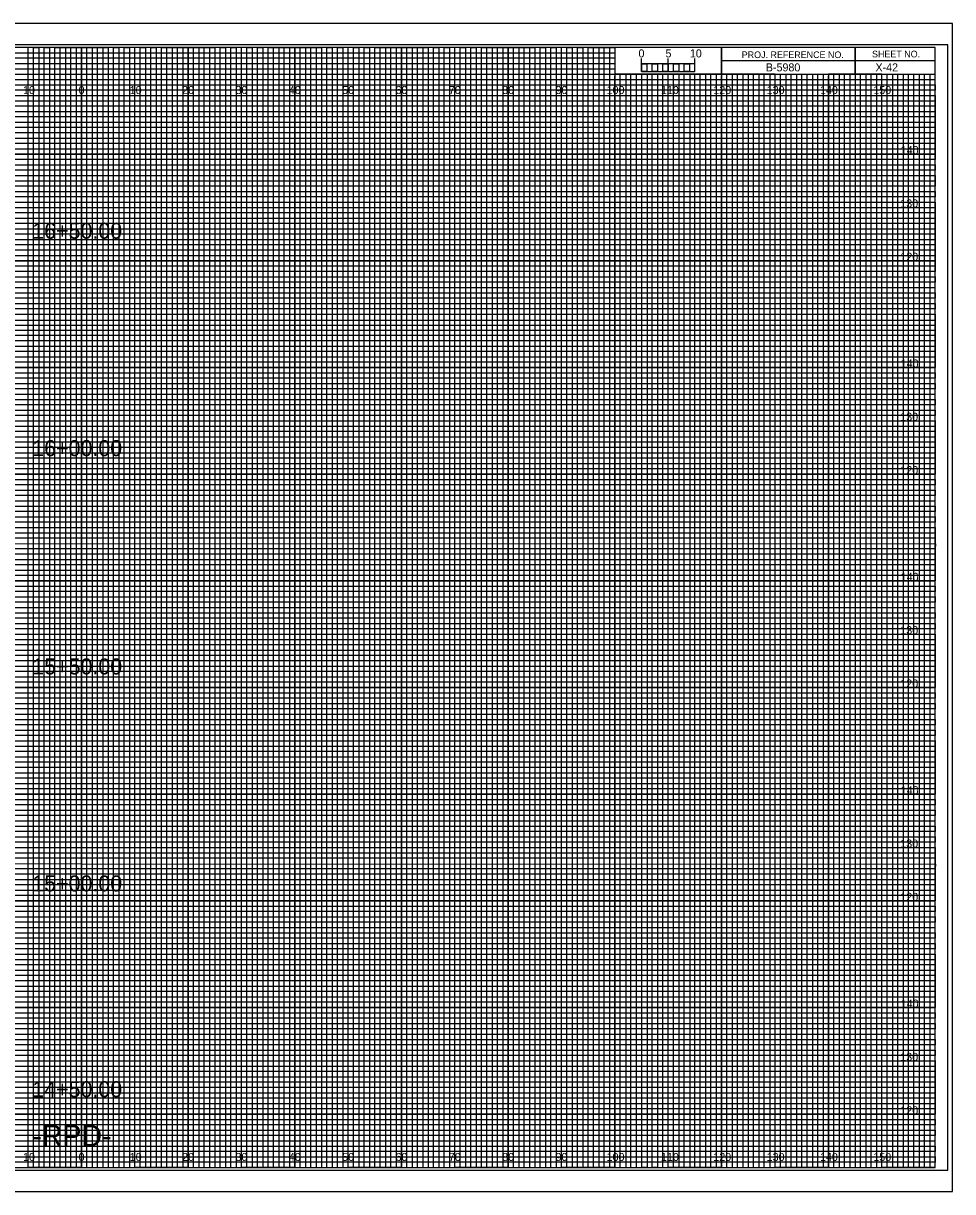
# Model space of a CAD drawing. Extents: x -13 to 323, y -5 to 874.
# Drawn here: x 149.1 to 323.3, y -4.5 to 214.5 of the extents above; entities that cross this region are included whole.
import ezdxf

# ---------------------------------------------------------------- set-up
doc = ezdxf.new("R2010")
doc.units = 0
for name, color, linetype in [('Exist Cross Section Cell', 7, 'Continuous'), ('Exist XS Center Line Elevation Label', 7, 'Continuous'), ('Exist XS Ground Line', 7, 'Continuous'), ('Prop CMT Conc Surface', 7, 'Continuous'), ('Prop CMT Concrete Structures', 7, 'Continuous'), ('Prop CMT Pvmt Course 1', 7, 'Continuous'), ('Prop CMT Pvmt Course 1 CG', 7, 'Continuous'), ('Prop CMT Pvmt Course 2', 7, 'Continuous'), ('Prop CMT Pvmt Course 3', 7, 'Continuous'), ('Prop CMT Pvmt Surface', 7, 'Continuous'), ('Prop CMT Pvmt Surface Shoulder', 7, 'Continuous'), ('Prop CMT Shld Paved Course 1', 7, 'Continuous'), ('Prop CMT Shld Paved Course 2', 7, 'Continuous'), ('Prop CMT Shld Paved Course 3', 7, 'Continuous'), ('Prop CMT Slope Grass', 7, 'Continuous'), ('Prop CMT Subgrade Earthwork', 7, 'Continuous'), ('Scratch_Level_1', 7, 'Continuous')]:
    doc.layers.add(name, color=color, linetype=linetype)

msp = doc.modelspace()

# ---------------------------------------------------------------- linework, layer by layer
at = {"layer": 'Exist XS Center Line Elevation Label'}
for points in [[(145, 0), (155, 0), (155, 210), (165, 210), (165, 0), (175, 0), (175, 210), (185, 210), (185, 0), (195, 0), (195, 210), (205, 210), (205, 0), (215, 0), (215, 210), (225, 210), (225, 0), (235, 0), (235, 210), (245, 210), (245, 0), (255, 0), (255, 210), (259.93, 210), (260, 210), (260, 205), (264.99, 205), (264.99, 0), (275, 0), (275, 205), (285, 205), (285, 0), (295, 0), (295, 205), (305, 205), (305, 0), (315, 0), (315, 205)], [(0, 205), (275, 205)], [(0, 185), (320, 185), (320, 195), (0, 195)], [(0, 165), (320, 165), (320, 175), (0, 175)], [(0, 145), (320, 145), (320, 155), (0, 155)], [(0, 125), (320, 125), (320, 135), (0, 135)], [(0, 105), (320, 105), (320, 115), (0, 115)], [(0, 85), (320, 85), (320, 95), (0, 95)], [(0, 65), (320, 65), (320, 75), (0, 75)], [(0, 45), (320, 45), (320, 55), (0, 55)], [(0, 25), (320, 25), (320, 35), (0, 35)], [(0, 5), (320, 5), (320, 15), (0, 15)]]:
    msp.add_lwpolyline(points, dxfattribs=at)
at = {"layer": 'Exist XS Ground Line'}
for p, q in [((150, 210), (140, 210)), ((150, 0), (150, 210)), ((170, 210), (160, 210)), ((160, 210), (160, 0)), ((170, 0), (170, 210)), ((190, 210), (180, 210)), ((180, 210), (180, 0)), ((190, 0), (190, 210)), ((210, 210), (200, 210)), ((200, 210), (200, 0)), ((210, 0), (210, 210)), ((230, 210), (220, 210)), ((220, 210), (220, 0)), ((230, 0), (230, 210)), ((250, 210), (240, 210)), ((240, 210), (240, 0)), ((250, 0), (250, 210)), ((260, 210), (260, 0)), ((270, 0), (270, 205)), ((290, 205), (280, 205)), ((280, 205), (280, 0)), ((290, 0), (290, 205)), ((310, 205), (300, 205)), ((300, 205), (300, 0)), ((310, 0), (310, 205)), ((160, 0), (150, 0)), ((180, 0), (170, 0)), ((200, 0), (190, 0)), ((220, 0), (210, 0)), ((240, 0), (230, 0)), ((260, 0), (250, 0)), ((280, 0), (270, 0)), ((300, 0), (290, 0)), ((320, 0), (310, 0)), ((320, 0), (320, 0))]:
    msp.add_line(p, q, dxfattribs=at)
for points in [[(0, 200), (320, 200), (320, 190), (0, 190)], [(0, 180), (320, 180), (320, 170), (0, 170)], [(0, 160), (320, 160), (320, 150), (0, 150)], [(0, 140), (320, 140), (320, 130), (0, 130)], [(0, 120), (320, 120), (320, 110), (0, 110)], [(0, 100), (320, 100), (320, 90), (0, 90)], [(0, 80), (320, 80), (320, 70), (0, 70)], [(0, 60), (320, 60), (320, 50), (0, 50)], [(0, 40), (320, 40), (320, 30), (0, 30)], [(0, 20), (320, 20), (320, 10), (0, 10)]]:
    msp.add_lwpolyline(points, dxfattribs=at)
at = {"layer": 'Prop CMT Pvmt Course 2'}
for p, q in [((265, 205.49), (265, 207.9)), ((265, 206.9), (265, 207.9)), ((270, 205.49), (270, 207.9)), ((275, 205.49), (275, 207.9)), ((275, 206.9), (275, 207.9))]:
    msp.add_line(p, q, dxfattribs=at)
for points in [[(275, 206.9), (265, 206.9), (265, 205.49), (275, 205.49)], [(265, 206.9), (266, 206.9), (266, 205.49), (265, 205.49)], [(267, 206.9), (268, 206.9), (268, 205.49), (267, 205.49)], [(269, 206.9), (270, 206.9), (270, 205.49), (269, 205.49)], [(271, 206.9), (272, 206.9), (272, 205.49), (271, 205.49)], [(273, 206.9), (274, 206.9), (274, 205.49), (273, 205.49)]]:
    msp.add_lwpolyline(points, close=True, dxfattribs=at)
at = {"layer": 'Prop CMT Pvmt Course 3'}
msp.add_lwpolyline([(-13.4, -4.5), (323.3, -4.5), (323.3, 214.5), (-13.4, 214.5)], close=True, dxfattribs=at)
at = {"layer": 'Prop CMT Pvmt Surface'}
for p, q in [((150, 0), (150, 210)), ((160, 0), (160, 210)), ((170, 0), (170, 210)), ((180, 0), (180, 210)), ((190, 0), (190, 210)), ((200, 0), (200, 210)), ((210, 0), (210, 210)), ((220, 0), (220, 210)), ((230, 0), (230, 210)), ((240, 0), (240, 210)), ((250, 0), (250, 210)), ((260, 0), (260, 204.69)), ((270, 0), (270, 204.69)), ((280, 0), (280, 204.69)), ((290, 0), (290, 204.69)), ((300, 0), (300, 204.69)), ((310, 0), (310, 204.69)), ((0, 200), (320, 200)), ((0, 190), (320, 190)), ((0, 180), (320, 180)), ((0, 170), (320, 170)), ((0, 160), (320, 160)), ((0, 150), (320, 150)), ((0, 140), (320, 140)), ((0, 130), (320, 130)), ((0, 120), (320, 120)), ((0, 110), (320, 110)), ((0, 100), (320, 100)), ((0, 90), (320, 90)), ((0, 80), (320, 80)), ((0, 70), (320, 70)), ((0, 60), (320, 60)), ((0, 50), (320, 50)), ((0, 40), (320, 40)), ((0, 30), (320, 30)), ((0, 20), (320, 20)), ((0, 10), (320, 10))]:
    msp.add_line(p, q, dxfattribs=at)
at = {"layer": 'Prop CMT Pvmt Surface Shoulder'}
for p, q in [((323.3, 214.5), (-13.4, 214.5)), ((-13.4, -4.5), (323.3, -4.5))]:
    msp.add_line(p, q, dxfattribs=at)
at = {"layer": 'Prop CMT Shld Paved Course 1'}
for p, q in [((0, 209), (260, 209)), ((260, 209), (260, 207.98)), ((260, 207.98), (0, 207.98)), ((0, 207), (260, 207)), ((260, 205.89), (0, 205.89)), ((260, 207), (260, 205.89)), ((0, 204), (320, 204))]:
    msp.add_line(p, q, dxfattribs=at)
for points in [[(0, 203), (270, 203), (320, 203), (320, 202), (0, 202)], [(0, 201), (320, 201), (320, 199), (0, 199)], [(0, 198), (320, 198), (320, 197), (0, 196.98)], [(0, 196), (320, 196), (320, 194), (0, 194)], [(0, 193), (320, 193), (320, 192), (0, 192)], [(0, 191), (320, 191), (320, 189), (0, 189)], [(0, 188), (320, 188), (320, 187), (0, 187)], [(0, 186), (320, 186), (320, 184), (0, 184)], [(0, 183), (320, 183), (320, 182), (0, 182)], [(0, 181), (320, 181), (320, 179), (0, 179)], [(0, 178), (320, 178), (320, 177), (0, 177)], [(0, 176), (320, 176), (320, 173.95), (320, 173), (320, 172), (0, 172)], [(0, 174), (320, 174), (320, 173), (0, 173)], [(0, 171), (320, 171), (320, 169), (0, 169.03)], [(0, 169.03), (320, 169), (320, 168), (0, 168)], [(0, 167), (320, 167), (320, 166), (0, 166)], [(0, 164), (320, 164), (320, 163), (0, 163)], [(0, 162), (320, 162), (320, 161), (0, 161)], [(-0.07, 158.89), (320, 158.89), (320, 157.88), (-0.07, 157.88)], [(0, 157), (320, 157), (320, 156), (0, 156)], [(0, 154), (320, 154), (320, 153), (0, 153)], [(0, 152), (320, 152), (320, 151), (0, 151)], [(0, 149), (320, 149), (320, 148), (0, 148)], [(0, 147), (320, 147), (320, 146), (0, 146)], [(0, 144), (320, 144), (320, 143), (0, 143)], [(0, 142), (320, 142), (320, 141), (0, 141)], [(0, 139), (320, 139), (319.99, 137.98), (0, 138)], [(0, 137), (320, 137), (320, 136), (0, 136)], [(0, 134), (320, 134), (320, 133), (0, 133)], [(0, 132), (320, 132), (320, 131), (0, 131)], [(0, 129), (320, 129), (320, 128), (0, 128)], [(0, 127), (320, 127), (320, 126), (0, 126)], [(0, 124), (320, 124), (320, 123), (0, 123)], [(0, 122), (320, 122), (320, 121), (0, 121)], [(0, 119), (320, 119), (320, 118), (0, 118)], [(0, 116.99), (320.07, 116.91), (320, 116), (0, 116)], [(0, 114), (320, 114), (320, 113), (0, 113)], [(0, 112), (320, 112), (320, 111), (0, 111)], [(0, 109), (320, 109), (320, 108), (0, 108)], [(0, 107), (320, 107), (320, 106), (0, 106)], [(0, 104), (320, 104), (320, 103), (0, 103)], [(0, 102), (320, 102), (320, 101), (0, 101)], [(0, 99), (320, 99), (320, 98), (0, 98)], [(0, 97), (320, 97), (320, 96), (0, 96)], [(0, 94), (320, 94), (320, 93), (0, 93)], [(0, 92), (320, 92), (320, 91), (0, 91)], [(0, 89), (320, 89), (320, 88), (0, 88)], [(0, 87), (320, 87), (320, 86), (0, 86)], [(0, 84), (320, 84), (320, 83), (0, 83)], [(0, 82), (320, 82), (320, 81), (0, 81)], [(0, 79), (320, 79), (319.99, 77.98), (0, 78)], [(0, 77), (320, 77), (320, 76), (0, 76)], [(0, 74), (320, 74), (320, 73), (0, 73)], [(0, 72), (320, 72), (320, 71), (0, 71)], [(0, 69), (320, 69), (320, 68), (0, 68)], [(0, 67), (320, 67), (320, 66), (0, 66)], [(0, 64), (320, 64), (320, 63), (0, 63)], [(0, 62), (320, 62), (320, 61), (0, 61)], [(0, 59), (320, 59), (320, 58), (0, 58)], [(0, 56.99), (320.07, 56.91), (320, 56), (0, 56)], [(0, 54), (320, 54), (320, 53), (0, 53)], [(0, 52), (320, 52), (320, 51), (0, 51)], [(0, 49), (320, 49), (320, 48), (0, 48)], [(0, 47), (320, 47), (320, 46), (0, 46)], [(0, 44), (320, 44), (320, 43), (0, 43)], [(0, 42), (320, 42), (320, 41), (0, 41)], [(0, 39), (320, 39), (320, 38), (0, 38)], [(0, 37), (320, 37), (320, 36), (0, 36)], [(0, 34), (320, 34), (320, 33), (0, 33)], [(0, 32), (320, 32), (320, 31), (0, 31)], [(0, 29), (320, 29), (320, 28), (0, 28)], [(0, 27), (320, 27), (320, 26), (0, 26)], [(0, 24), (320, 24), (320, 23), (0, 23)], [(0, 22), (320, 22), (320, 21), (0, 21)], [(0, 19), (320, 19), (320, 18), (0, 18)], [(0, 17), (320, 17), (320, 16), (0, 16)], [(0, 14), (320, 14), (320, 13), (0, 13)], [(0, 12), (320, 12), (320, 11), (0, 11)], [(0, 9), (320, 9), (320, 8), (0, 8)], [(0, 7), (320, 7), (320, 6), (0, 6)], [(0, 4), (320, 4), (320, 3), (0, 3)], [(0, 2), (320, 2), (320, 1), (0, 1)]]:
    msp.add_lwpolyline(points, dxfattribs=at)
at = {"layer": 'Prop CMT Shld Paved Course 2'}
for p, q in [((305, 210), (305, 205)), ((305, 205), (305, 210)), ((280, 207.5), (280, 205)), ((320, 207.49), (280, 207.49)), ((280, 205), (320, 205))]:
    msp.add_line(p, q, dxfattribs=at)
for points in [[(320, 210), (0, 210), (0, 0), (320, 0)], [(280, 210), (260, 210), (260, 205.03), (280, 205.03)], [(320, 210), (280, 210), (280, 205), (320, 205)]]:
    msp.add_lwpolyline(points, close=True, dxfattribs=at)
at = {"layer": 'Prop CMT Shld Paved Course 3'}
for p, q in [((267, 205), (266.01, 205)), ((266.01, 205), (266.01, 0)), ((267, 0), (267, 205)), ((269, 205), (268, 205)), ((268, 205), (268, 0)), ((269, 0), (269, 205)), ((266.01, 0), (265, 0)), ((268, 0), (267, 0))]:
    msp.add_line(p, q, dxfattribs=at)
for points in [[(150, 0), (151, 0), (151, 210), (152, 210), (152, 0)], [(152, 0), (153, 0), (153, 210), (154, 210), (154, 0)], [(155, 0), (156, 0), (156, 210), (157, 210), (157, 0)], [(157, 0), (158, 0), (158, 210), (159, 210), (159, 0)], [(160, 0), (161, 0), (161, 210), (162, 210), (162, 0)], [(162, 0), (163, 0), (163, 210), (164, 210), (164, 0)], [(165, 0), (166, 0), (166, 210), (167, 210), (167, 0)], [(167, 0), (168, 0), (168, 210), (169, 210), (169, 0)], [(170, 0), (171, 0), (171, 210), (172, 210), (172, 0)], [(172, 0), (173, 0), (173, 210), (174, 210), (174, 0)], [(175, 0), (176, 0), (176, 210), (177, 210), (177, 0)], [(177, 0), (178, 0), (178, 210), (179, 210), (179, 0)], [(180, 0), (181, 0), (181, 210), (182, 210), (182, 0)], [(182, 0), (183, 0), (183, 210), (184, 210), (184, 0)], [(185, 0), (186, 0), (186, 210), (187, 210), (187, 0)], [(187, 0), (188, 0), (188, 210), (189, 210), (189, 0)], [(190, 0), (191, 0), (191, 210), (192, 210), (192, 0)], [(192, 0), (193, 0), (193, 210), (194, 210), (194, 0)], [(195, 0), (196, 0), (196, 210), (197, 210), (197, 0)], [(197, 0), (198, 0), (198, 210), (199, 210), (199, 0)], [(200, 0), (201, 0), (201, 210), (202, 210), (202, 0)], [(202, 0), (203, 0), (203, 210), (204, 210), (204, 0)], [(205, 0), (206, 0), (206, 210), (207, 210), (207, 0)], [(207, 0), (208, 0), (208, 210), (209, 210), (209, 0)], [(210, 0), (211, 0), (211, 210), (212, 210), (212, 0)], [(212, 0), (213, 0), (213, 210), (214, 210), (214, 0)], [(215, 0), (216, 0), (216, 210), (217, 210), (217, 0)], [(217, 0), (218, 0), (218, 210), (219, 210), (219, 0)], [(220, 0), (221, 0), (221, 210), (222, 210), (222, 0)], [(222, 0), (223, 0), (223, 210), (224, 210), (224, 0)], [(225, 0), (226, 0), (226, 210), (227, 210), (227, 0)], [(227, 0), (228, 0), (228, 210), (229, 210), (229, 0)], [(230, 0), (231, 0), (231, 210), (232, 210), (232, 0)], [(232, 0), (233, 0), (233, 210), (234, 210), (234, 0)], [(235, 0), (236, 0), (236, 210), (237, 210), (237, 0)], [(237, 0), (238, 0), (238, 210), (239, 210), (239, 0)], [(240, 0), (241, 0), (241, 210), (242, 210), (242, 0)], [(242, 0), (243, 0), (243, 210), (244, 210), (244, 0)], [(245, 0), (246, 0), (246, 210), (247, 210), (247, 0)], [(247, 0), (248, 0), (248, 210), (249, 210), (249, 0)], [(250, 0), (251, 0), (251, 210), (252, 210), (252, 0)], [(252, 0), (253, 0), (253, 210), (254, 210), (254, 0)], [(255, 0), (256, 0), (256, 210), (257, 210), (257, 0)], [(257, 0), (258, 0), (258, 210), (259, 210), (259, 0)], [(260, 0), (261, 0), (261, 205), (262.02, 205), (262.02, 0)], [(262, 0), (263, 0), (263, 205), (263.99, 205), (263.99, 0)], [(270, 0), (270.98, 0), (270.98, 205), (272, 205), (272, 0)], [(272, 0), (273, 0), (273, 205), (274.05, 205), (274.05, 0)], [(275, 0), (276, 0), (276, 205), (277, 205), (277, 0)], [(277, 0), (278, 0), (278, 205), (279, 205), (279, 0)], [(280, 0), (281, 0), (281, 205), (282, 205), (282, 0)], [(282, 0), (283, 0), (283, 205), (284, 205), (284, 0)], [(285, 0), (286, 0), (286, 205), (287, 205), (287, 0)], [(287, 0), (288, 0), (288, 205), (289, 205), (289, 0)], [(290, 0), (291, 0), (291, 205), (292, 205), (292, 0)], [(292, 0), (293, 0), (293, 205), (294, 205), (294, 0)], [(295, 0), (296, 0), (296, 205), (297, 205), (297, 0)], [(297, 0), (298, 0), (298, 205), (299, 205), (299, 0)], [(300, 0), (301, 0), (301, 205), (302, 205), (302, 0)], [(302, 0), (303, 0), (303, 205), (304, 205), (304, 0)], [(305, 0), (306, 0), (306, 205), (307, 205), (307, 0)], [(307, 0), (308, 0), (308, 205), (309, 205), (309, 0)], [(310, 0), (311, 0), (311, 205), (312, 205), (312, 0)], [(312, 0), (313, 0), (313, 205), (314, 205), (314, 0)], [(315, 0), (316, 0), (316, 205), (317, 205), (317, 0)], [(317, 0), (318, 0), (318, 205), (319, 205), (319, 0)]]:
    msp.add_lwpolyline(points, dxfattribs=at)
at = {"layer": 'Prop CMT Subgrade Earthwork'}
msp.add_lwpolyline([(-10.8, -0.5), (322.4, -0.5), (322.4, 210.5), (-10.8, 210.5)], close=True, dxfattribs=at)

# ---------------------------------------------------------------- texts
at = {"layer": 'Exist Cross Section Cell'}
for s, p in [('10', (149.04, 201.25)), ('0', (159.45, 201.25)), ('0', (159.45, 201.25)), ('10', (169.04, 201.25)), ('20', (178.86, 201.25)), ('30', (188.86, 201.25)), ('40', (198.86, 201.25)), ('50', (208.86, 201.25)), ('60', (218.86, 201.25)), ('70', (228.86, 201.25)), ('80', (238.86, 201.25)), ('90', (248.86, 201.25)), ('100', (258.44, 201.25)), ('110', (268.62, 201.25)), ('120', (278.44, 201.25)), ('130', (288.44, 201.25)), ('140', (298.44, 201.25)), ('150', (308.44, 201.25)), ('10', (149.04, 1.25)), ('0', (159.45, 1.25)), ('0', (159.45, 1.25)), ('10', (169.04, 1.25)), ('20', (178.86, 1.25)), ('30', (188.86, 1.25)), ('40', (198.86, 1.25)), ('50', (208.86, 1.25)), ('60', (218.86, 1.25)), ('70', (228.86, 1.25)), ('80', (238.86, 1.25)), ('90', (248.86, 1.25)), ('100', (258.44, 1.25)), ('110', (268.62, 1.25)), ('120', (278.44, 1.25)), ('130', (288.44, 1.25)), ('140', (298.44, 1.25)), ('150', (308.44, 1.25))]:
    msp.add_text(s, height=1.5, dxfattribs=at).set_placement(p)
at = {"layer": 'Prop CMT Conc Surface'}
for s, p in [('5', (269.47, 208.12)), ('10', (274.04, 208.12))]:
    msp.add_text(s, height=1.5, dxfattribs=at).set_placement(p)
at = {"layer": 'Prop CMT Concrete Structures'}
msp.add_text('B-5980', height=1.5, dxfattribs=at).set_placement((288.28, 205.5))
at = {"layer": 'Prop CMT Pvmt Course 1'}
for s, p in [('140', (313.57, 190)), ('130', (313.49, 180)), ('120', (313.5, 170)), ('140', (313.57, 150)), ('130', (313.49, 140)), ('120', (313.5, 130)), ('140', (313.57, 110)), ('130', (313.49, 100)), ('120', (313.5, 90)), ('140', (313.57, 70)), ('130', (313.49, 60)), ('120', (313.5, 50)), ('140', (313.57, 30)), ('130', (313.49, 20)), ('120', (313.5, 10))]:
    msp.add_text(s, height=1.5, dxfattribs=at).set_placement(p)
at = {"layer": 'Prop CMT Pvmt Course 1 CG'}
msp.add_text('-RPD-', height=4, dxfattribs=at).set_placement((150.78, 4))
at = {"layer": 'Prop CMT Pvmt Course 2'}
msp.add_text('0', height=1.5, dxfattribs=at).set_placement((264.41, 208.12))
at = {"layer": 'Prop CMT Shld Paved Course 2'}
for s, p in [('PROJ. REFERENCE NO.', (283.77, 207.99)), ('SHEET NO.', (308.19, 208.12))]:
    msp.add_text(s, height=1.25, dxfattribs=at).set_placement(p)
at = {"layer": 'Prop CMT Slope Grass'}
for s, p in [('16+50.00', (150.77, 174.13)), ('16+00.00', (150.77, 133.38)), ('15+50.00', (150.77, 92.46)), ('15+00.00', (150.77, 51.78)), ('14+50.00', (150.77, 13.2))]:
    msp.add_text(s, height=3, dxfattribs=at).set_placement(p)
at = {"layer": 'Scratch_Level_1'}
msp.add_text('X-42', height=1.5, dxfattribs=at).set_placement((308.83, 205.5))

doc.saveas('drawing.dxf')
